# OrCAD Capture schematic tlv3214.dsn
size A
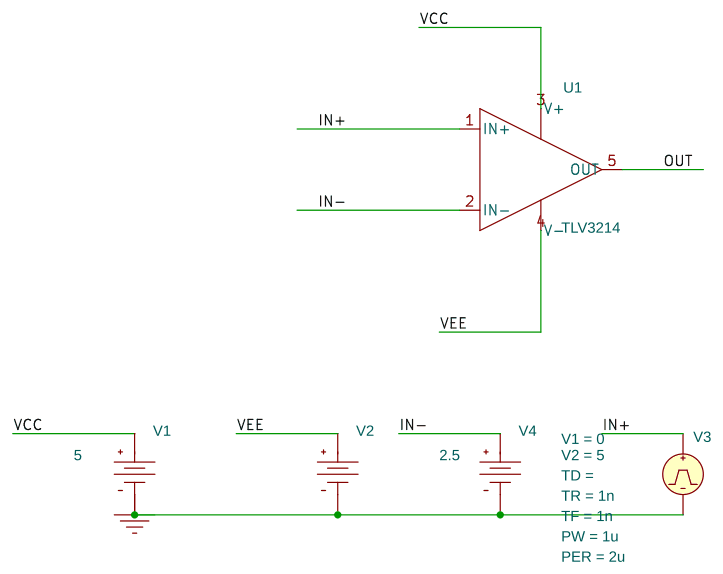
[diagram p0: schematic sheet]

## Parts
U1  TLV3214
V1  VDC
V2  VDC
V3  VPULSE
V4  VDC

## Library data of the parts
U1 = TLV3214
V1 = VDC: DC: 5
V2 = VDC
V3 = VPULSE: PER: 2u; PW: 1u; TF: 1n; TR: 1n; V1: 0; V2: 5
V4 = VDC: DC: 2.5

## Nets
VCC: U1.3(V+) V1.0(+)
VEE: U1.4(V-) V2.0(+)
0: V1.1(-) V2.1(-) V3.2(-) V4.1(-)
IN+: U1.1(IN+) V3.1(+)
IN-: U1.2(IN-) V4.0(+)
OUT: U1.5(OUT)
